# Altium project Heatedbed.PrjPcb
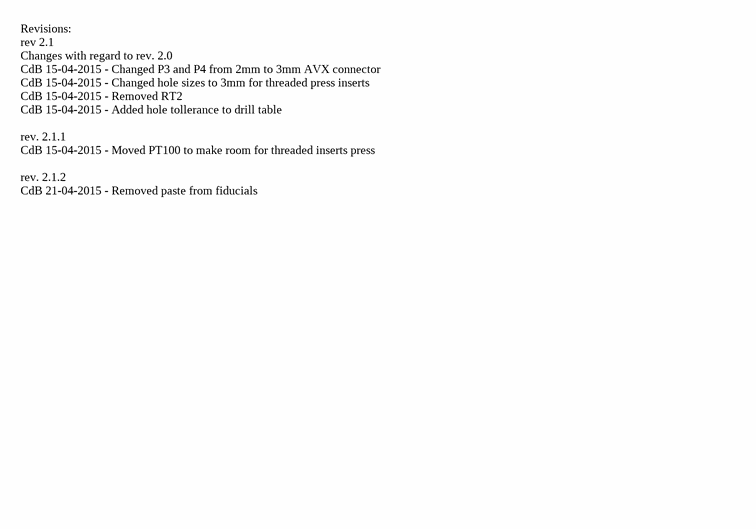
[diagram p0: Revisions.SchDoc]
2 sheets, 8 parts. Net scope: global (net labels, ports and power ports of the same name join across sheets).
Board file: Heatedbed.PcbDoc
Sheets:
  Revisions.SchDoc
  Heatedbed.SchDoc

## Sheet Revisions.SchDoc: Heated bed
size A4; CompanyName: Ultimaker B.V.; DrawnBy: Coen de Boer; Engineer: Coen de Boer; Revision: 2.1.2

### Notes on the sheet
- Revisions:
  rev 2.1
  Changes with regard to rev. 2.0
  CdB 15-04-2015 - Changed P3 and P4 from 2mm to 3mm AVX connector
  CdB 15-04-2015 - Changed hole sizes to 3mm for threaded press inserts
  CdB 15-04-2015 - Removed RT2
  CdB 15-04-2015 - Added hole tollerance to drill table
  rev. 2.1.1
  CdB 15-04-2015 - Moved PT100 to make room for threaded inserts press
  rev. 2.1.2
  CdB 21-04-2015 - Removed paste from fiducials

## Sheet Heatedbed.SchDoc: Heated bed
size A4; CompanyName: Ultimaker B.V.; DrawnBy: Coen de Boer; Engineer: Coen de Boer; Revision: 2.1.2
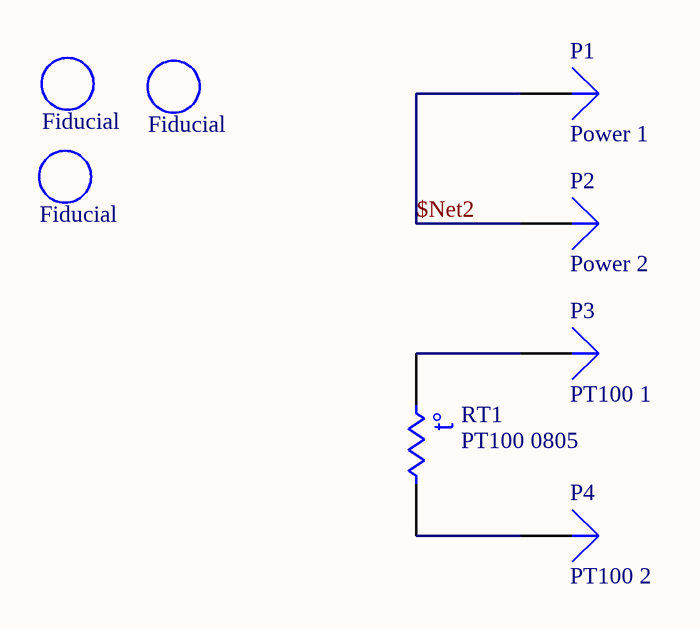
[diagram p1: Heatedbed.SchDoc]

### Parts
Fid1  Fiducial  [Fiducial]  (no BOM)
Fid2  Fiducial  [Fiducial]  (no BOM)
Fid3  Fiducial  [Fiducial]  (no BOM)
P1  Power 1  [AVX Poke home contact]
P2  Power 2  [AVX Poke home contact]
P3  PT100 1  [AVX POKE HOME CONTACT 3MM]
P4  PT100 2  [AVX POKE HOME CONTACT 3MM]
RT1  PT100 0805  [6-0805_M]

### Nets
$Net2: P1.1 P2.1
NetP3_1: P3.1 RT1.1
NetP4_1: P4.1 RT1.2

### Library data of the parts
Fid1-Fid3 = Library_MISC-0003
P1 P2 = Plug: Mfg: AVX; Mfg code: 70-9296-001-004-006
P3 P4 = Plug: Mfg: AVX; Mfg code: 70-9296-001-003-006
RT1 = Res Thermal: Thermistor; Mfg: IST INNOVATIVE SENSOR TECHNOLOGY; Mfg code: P0K1.0805.2P.B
